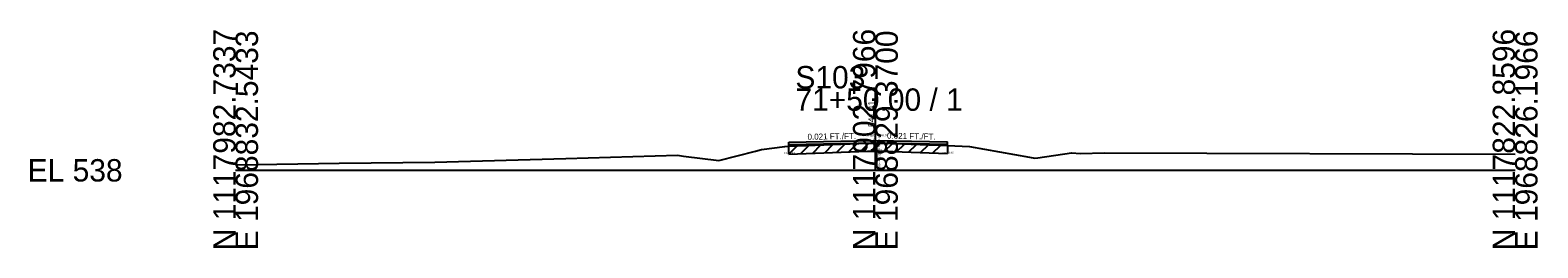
# Model space of a CAD drawing. Extents: x -26 to 163, y -10 to 24018.
# Drawn here: x -25.7 to 162.8, y 19490.3 to 19517.5 of the extents above; entities that cross this region are included whole.
import ezdxf

# ---------------------------------------------------------------- set-up
doc = ezdxf.new("R2010")
doc.units = 0
for name, color, linetype in [('RD_GPK_XS_Cell', 7, 'Continuous'), ('RD_XS_ExGround', 7, 'Continuous'), ('RD_XS_ExPaveRet', 7, 'Continuous'), ('RD_XS_Misc_Line', 7, 'Continuous'), ('RD_XS_PaveOvlay_CP', 7, 'Continuous'), ('RD_XS_TX_Elev_EX', 7, 'Continuous'), ('RD_XS_TX_ExEOP', 7, 'Continuous'), ('RD_XS_TX_Notes', 7, 'Continuous'), ('RD_XS_TX_Profile', 7, 'Continuous'), ('RD_XS_TX_Slope', 7, 'Continuous')]:
    doc.layers.add(name, color=color, linetype=linetype)

msp = doc.modelspace()

# ---------------------------------------------------------------- linework, layer by layer
at = {"layer": 'RD_GPK_XS_Cell'}
for p, q in [((80, 19500), (80, 19510.24)), ((0, 19500), (80, 19500)), ((80, 19500), (160, 19500))]:
    msp.add_line(p, q, dxfattribs=at)
at = {"layer": 'RD_XS_ExGround'}
msp.add_lwpolyline([(0, 19500.67), (12.96, 19500.89), (24.91, 19501.02), (41.3, 19501.48), (55.24, 19501.88), (56.02, 19501.77), (60.41, 19501.23), (65, 19502.41), (65.75, 19502.6), (68.67, 19502.98), (69.16, 19503.04), (79.02, 19503.38), (80.14, 19503.41), (81.04, 19503.38), (89.01, 19503.09), (91.77, 19502.96), (99.26, 19501.64), (99.96, 19501.52), (100.32, 19501.57), (104.53, 19502.17), (105.63, 19502.12), (108.59, 19502.18), (160, 19502.01)], dxfattribs=at)
at = {"layer": 'RD_XS_ExPaveRet'}
for p, q in [((69.16, 19502.04), (70.2, 19503.08)), ((69.16, 19502.04), (69.16, 19503.04)), ((69.16, 19502.04), (79.02, 19502.38)), ((70.66, 19502.09), (71.7, 19503.13)), ((72.16, 19502.15), (73.2, 19503.18)), ((73.66, 19502.2), (74.7, 19503.23)), ((75.16, 19502.25), (76.2, 19503.28)), ((76.66, 19502.3), (77.7, 19503.33)), ((78.16, 19502.35), (79.2, 19503.38)), ((79.02, 19502.38), (80.14, 19502.41)), ((79.66, 19502.4), (80.66, 19503.4)), ((80.14, 19502.41), (81.04, 19502.38)), ((81.04, 19502.38), (89.01, 19502.09)), ((81.16, 19502.38), (82.13, 19503.34)), ((82.66, 19502.32), (83.63, 19503.29)), ((84.16, 19502.27), (85.13, 19503.23)), ((85.66, 19502.21), (86.63, 19503.18)), ((87.16, 19502.16), (88.13, 19503.12)), ((89.01, 19503.09), (89.01, 19502.09))]:
    msp.add_line(p, q, dxfattribs=at)
at = {"layer": 'RD_XS_Misc_Line'}
msp.add_line((80.14, 19503.41), (80.14, 19500.41), dxfattribs=at)
at = {"layer": 'RD_XS_PaveOvlay_CP'}
for p, q in [((69.16, 19503.51), (80, 19503.74)), ((80, 19503.74), (89.01, 19503.55)), ((69.16, 19503.04), (69.16, 19503.51)), ((80, 19503.41), (69.16, 19503.18)), ((89.01, 19503.22), (80, 19503.41)), ((89.01, 19503.09), (89.01, 19503.55))]:
    msp.add_line(p, q, dxfattribs=at)

# ---------------------------------------------------------------- texts
at = {"layer": 'RD_GPK_XS_Cell'}
for s, p in [('N 1117982.7337', (0, 19490)), ('E 1968832.5433', (2.8, 19490)), ('N 1117902.7966', (80, 19490)), ('E 1968829.3700', (82.8, 19490)), ('N 1117822.8596', (160, 19490)), ('E 1968826.1966', (162.8, 19490))]:
    msp.add_text(s, height=2.8, rotation=90, dxfattribs=at).set_placement(p)
for s, p in [('S103', (70, 19510.24)), ('71+50.00 / 1', (70, 19507.44)), ('EL 538', (-26, 19498.6))]:
    msp.add_text(s, height=2.8, dxfattribs=at).set_placement(p)
at = {"layer": 'RD_XS_TX_Elev_EX'}
msp.add_text('541.41', height=0.8, rotation=90, dxfattribs=at).set_placement((79.9, 19505.41))
at = {"layer": 'RD_XS_TX_ExEOP'}
for s, p in [('EOP-L', (69.11, 19503.51)), ('EOP-R', (88.96, 19503.55))]:
    msp.add_text(s, height=0.1, rotation=270, dxfattribs=at).set_placement(p)
at = {"layer": 'RD_XS_TX_Notes'}
for s, p in [('Elev. @CL = 541.74', (78.47, 19504.24)), (' dE= 0.47', (68.45, 19502.04)), (' dE= 0.33', (79.29, 19502.41)), (' dE= 0.46', (88.29, 19502.09))]:
    msp.add_text(s, height=0.25, dxfattribs=at).set_placement(p)
msp.add_text(' Min. Distance @CP = -0.01', height=0.25, rotation=270, dxfattribs=at).set_placement((80.39, 19504.5))
at = {"layer": 'RD_XS_TX_Profile'}
msp.add_text('CL', height=0.25, dxfattribs=at).set_placement((79.77, 19503.74))
at = {"layer": 'RD_XS_TX_Slope'}
for rotation, p in [(1.1916, (71.52, 19503.81)), (358.8084, (81.45, 19503.96))]:
    msp.add_text('0.021 FT./FT.', height=0.75, rotation=rotation, dxfattribs=at).set_placement(p)

doc.saveas('drawing.dxf')
